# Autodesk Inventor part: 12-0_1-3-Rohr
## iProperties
Created: 2006-01
Part Number: 12-0_1-3-Rohr
Document SubType Name: Blech
Designer: Armin Gräf
Stock Number: 12-0_1-3-Rohr
Author: Armin Gräf
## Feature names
1. Drehung1 [Revolution]
2. Drehung2 [Revolution]
3. Trennen1
